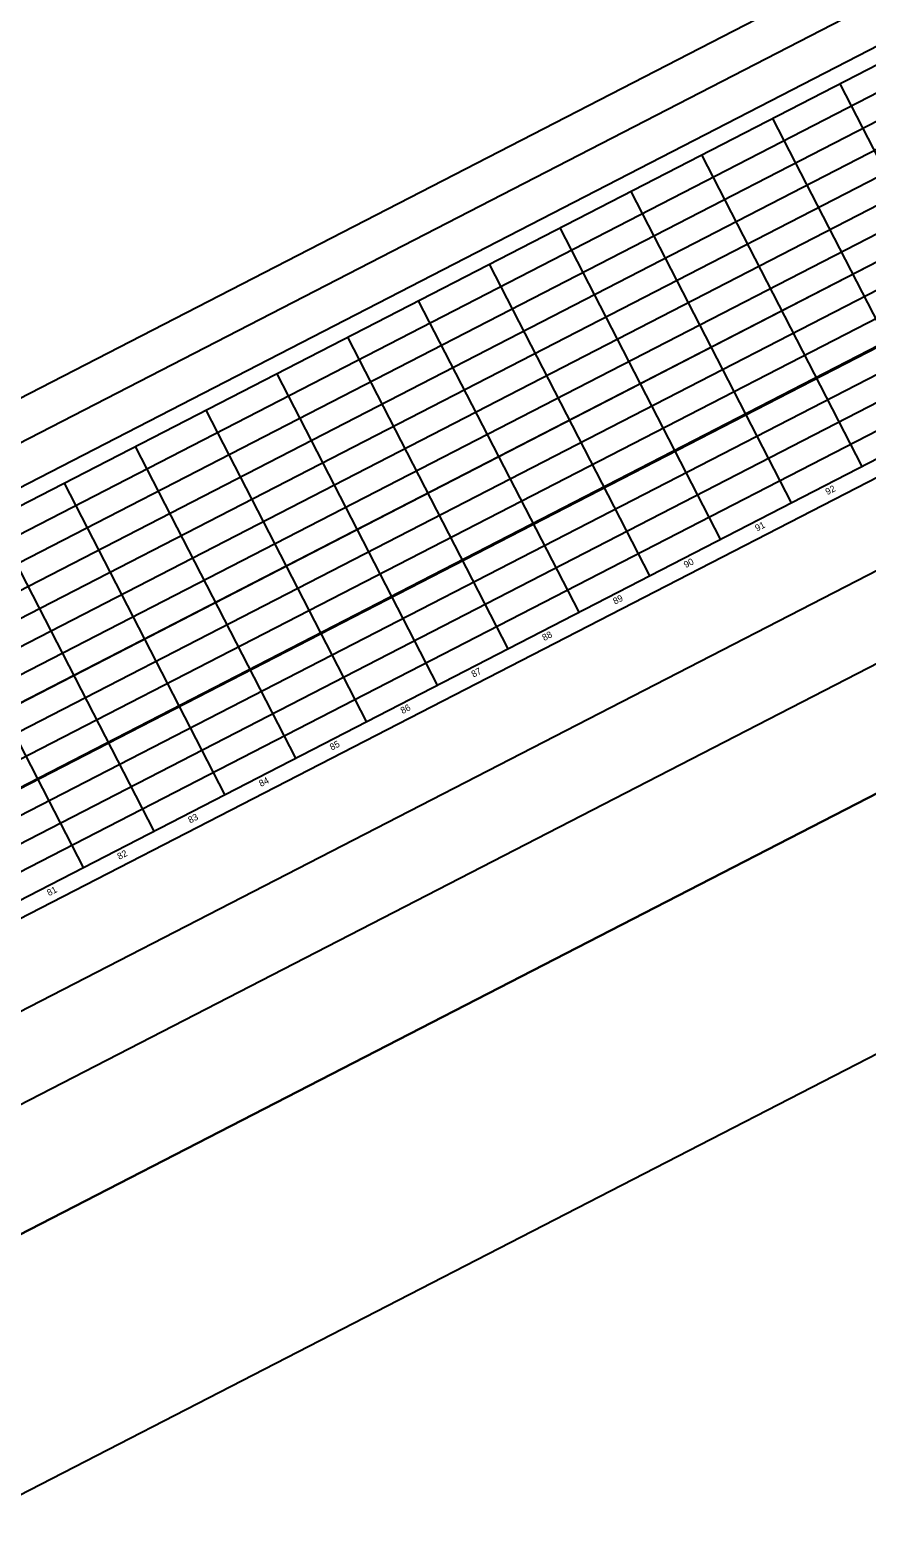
# Model space of a CAD drawing. Extents: x -886320 to -884760, y -1024172 to -1023483.
# Drawn here: x -885148.6 to -885022, y -1023827.5 to -1023599.4 of the extents above; entities that cross this region are included whole.
import ezdxf

# ---------------------------------------------------------------- set-up
doc = ezdxf.new("R2010")
doc.units = 0
for name, color, linetype in [('AGA__Netisknout', 7, 'Continuous'), ('Stavajici_betonova_draha', 7, 'Continuous'), ('Stavajici_betonova_draha_osa', 7, 'Continuous'), ('Stavajici_betonova_draha_Popis desky', 7, 'Continuous'), ('Stavajici_betonova_draha_Spára', 7, 'Continuous'), ('Stavajici_drahovy_system', 7, 'Continuous'), ('Stavajici_drahovy_system_osy', 7, 'Continuous'), ('Stavajici_drahovy_system_RWY_strip', 7, 'Continuous'), ('Stavajici_drahovy_system_TWY', 7, 'Continuous'), ('Stavajici_drahovy_system_TWY_osy', 7, 'Continuous')]:
    doc.layers.add(name, color=color, linetype=linetype)

msp = doc.modelspace()

# ---------------------------------------------------------------- linework, layer by layer
at = {"layer": 'AGA__Netisknout'}
msp.add_line((-886017.78, -1024147.99), (-884773.13, -1023507.02), dxfattribs=at)
at = {"layer": 'Stavajici_betonova_draha'}
for p, q in [((-886029.69, -1024124.32), (-884785.04, -1023483.35)), ((-886029.69, -1024124.32), (-884785.04, -1023483.35)), ((-886005.42, -1024171.44), (-884760.77, -1023530.47)), ((-886005.42, -1024171.44), (-884760.77, -1023530.47))]:
    msp.add_line(p, q, dxfattribs=at)
at = {"layer": 'Stavajici_betonova_draha_osa'}
msp.add_line((-886017.55, -1024147.88), (-884772.9, -1023506.91), dxfattribs=at)
at = {"layer": 'Stavajici_betonova_draha_Spára'}
for p, q in [((-886029.91, -1024124.43), (-884785.26, -1023483.46)), ((-886028.18, -1024127.8), (-884783.53, -1023486.82)), ((-886026.44, -1024131.16), (-884781.79, -1023490.19)), ((-886024.71, -1024134.53), (-884780.06, -1023493.56)), ((-886022.98, -1024137.89), (-884778.33, -1023496.92)), ((-886021.24, -1024141.26), (-884776.59, -1023500.29)), ((-886019.51, -1024144.63), (-884774.86, -1023503.65)), ((-886016.04, -1024151.36), (-884771.39, -1023510.39)), ((-886014.31, -1024154.72), (-884769.66, -1023513.75)), ((-886012.58, -1024158.09), (-884767.93, -1023517.12)), ((-886010.84, -1024161.46), (-884766.19, -1023520.48)), ((-886009.11, -1024164.82), (-884764.46, -1023523.85)), ((-886007.38, -1024168.19), (-884762.73, -1023527.21)), ((-886005.64, -1024171.55), (-884760.99, -1023530.58)), ((-885026.08, -1023607.48), (-885001.81, -1023654.6)), ((-885036.26, -1023612.72), (-885012, -1023659.84)), ((-885046.98, -1023618.24), (-885022.71, -1023665.36)), ((-885057.69, -1023623.76), (-885033.42, -1023670.88)), ((-885068.4, -1023629.27), (-885044.14, -1023676.39)), ((-885079.12, -1023634.79), (-885054.85, -1023681.91)), ((-885089.83, -1023640.31), (-885065.56, -1023687.43)), ((-885100.54, -1023645.82), (-885076.27, -1023692.95)), ((-885111.25, -1023651.34), (-885086.99, -1023698.46)), ((-885121.97, -1023656.86), (-885097.7, -1023703.98)), ((-885132.68, -1023662.37), (-885108.41, -1023709.5)), ((-885143.39, -1023667.89), (-885119.13, -1023715.01)), ((-885154.11, -1023673.41), (-885129.84, -1023720.53)), ((-885164.82, -1023678.92), (-885140.55, -1023726.05))]:
    msp.add_line(p, q, dxfattribs=at)
at = {"layer": 'Stavajici_drahovy_system'}
for p, q in [((-885721.56, -1024028.07), (-884864.53, -1023586.71)), ((-885726.12, -1024058.54), (-884837.08, -1023600.7)), ((-885744.78, -1024087.83), (-884802.4, -1023602.52)), ((-885728.75, -1024118.95), (-884786.38, -1023633.64))]:
    msp.add_line(p, q, dxfattribs=at)
at = {"layer": 'Stavajici_drahovy_system_osy'}
msp.add_line((-885731.84, -1024047.42), (-884842.81, -1023589.59), dxfattribs=at)
at = {"layer": 'Stavajici_drahovy_system_RWY_strip'}
for p, q in [((-885772.25, -1024034.49), (-884829.87, -1023549.18)), ((-884802.4, -1023602.52), (-885744.78, -1024087.83))]:
    msp.add_line(p, q, dxfattribs=at)
at = {"layer": 'Stavajici_drahovy_system_TWY'}
for p, q in [((-885887.27, -1024034.67), (-884885.91, -1023518.99)), ((-885748.12, -1023976.51), (-884891.09, -1023535.15))]:
    msp.add_line(p, q, dxfattribs=at)
at = {"layer": 'Stavajici_drahovy_system_TWY_osy'}
msp.add_line((-885886.7, -1024041.13), (-884883.17, -1023524.32), dxfattribs=at)

# ---------------------------------------------------------------- texts
at = {"layer": 'Stavajici_betonova_draha_Popis desky'}
for s, p in [('92', (-885027.93, -1023669.73)), ('91', (-885038.57, -1023675.22)), ('90', (-885049.36, -1023680.77)), ('89', (-885060.07, -1023686.29)), ('88', (-885070.78, -1023691.8)), ('87', (-885081.49, -1023697.32)), ('86', (-885092.21, -1023702.84)), ('85', (-885102.92, -1023708.36)), ('84', (-885113.63, -1023713.87)), ('83', (-885124.35, -1023719.39)), ('82', (-885135.06, -1023724.9)), ('81', (-885145.7, -1023730.39))]:
    msp.add_text(s, height=1, rotation=27.2477, dxfattribs=at).set_placement(p)

doc.saveas('drawing.dxf')
